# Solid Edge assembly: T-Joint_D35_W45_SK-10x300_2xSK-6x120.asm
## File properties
Author: fknapp
Template: iso metric assembly.asm
Last saved by: fknapp
Revision: 11
Application: Solid Edge
Username: fknapp
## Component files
T-Joint_D35_W45.par
SK Schraube 6x120_ohne_Gewinde.par
SK Schraube 10x300_ohne_Gewinde_22042020.par
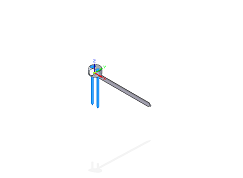
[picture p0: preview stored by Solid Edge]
